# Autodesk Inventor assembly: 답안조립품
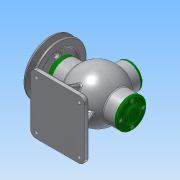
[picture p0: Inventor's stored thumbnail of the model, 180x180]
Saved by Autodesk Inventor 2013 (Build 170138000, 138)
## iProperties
Created: 2018-06
Part Number: 답안조립품
Document SubType Name: Assembly
Designer: Administrator
Author: Administrator
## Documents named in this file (19)
- C:\Users\Administrator\Desktop\480612V1004\답안조립품.iam
- C:\Users\Administrator\Desktop\480612V1004\본체.ipt
- C:\Users\Administrator\Desktop\480612V1004\V-벨트풀리.ipt
- C:\Users\Administrator\Desktop\480612V1004\너트 M8.ipt
- C:\Users\Administrator\Desktop\480612V1004\뒤커버.ipt
- C:\Users\Administrator\Desktop\480612V1004\멈춤링 15x1.ipt
- C:\Users\Administrator\Desktop\480612V1004\멈춤링 35x1.6.ipt
- 멈춤링 35x1.6.ipt
- C:\Users\Administrator\Desktop\480612V1004\베어링 6202.ipt
- 베어링 6202.ipt
- C:\Users\Administrator\Desktop\480612V1004\볼트 M4x12.ipt
- C:\Users\Administrator\Desktop\480612V1004\볼트 M4x16.ipt
- C:\Users\Administrator\Desktop\480612V1004\부시.ipt
- C:\Users\Administrator\Desktop\480612V1004\상부커버.ipt
- C:\Users\Administrator\Desktop\480612V1004\슬라이드.ipt
- C:\Users\Administrator\Desktop\480612V1004\앞커버.ipt
- C:\Users\Administrator\Desktop\480612V1004\오일 실 15 30 7.ipt
- C:\Users\Administrator\Desktop\480612V1004\키 4x4x12.ipt
- C:\Users\Administrator\Desktop\480612V1004\편심축.ipt
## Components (1 placed, 1 different names)
1. V-벨트풀리:1
